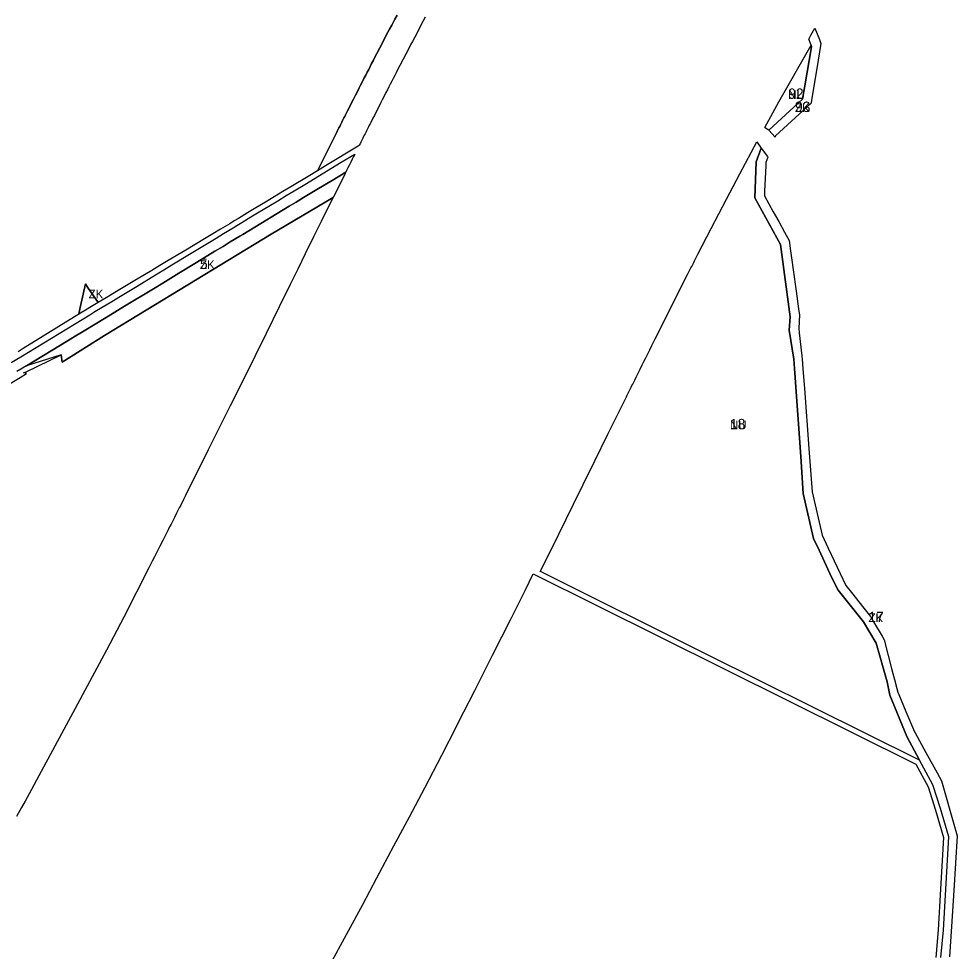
# Model space of a CAD drawing. Extents: x -537068 to -534056, y -1176840 to -1172401.
# Drawn here: x -536126 to -535584, y -1174218 to -1173679 of the extents above; entities that cross this region are included whole.
import ezdxf

# ---------------------------------------------------------------- set-up
doc = ezdxf.new("R2010")
doc.units = 0
for name, color, linetype in [('90640013', 7, 'Continuous'), ('90710013', 7, 'Continuous'), ('90710023', 7, 'Continuous'), ('90730023', 7, 'Continuous'), ('90750013', 7, 'Continuous'), ('ID_navrh', 7, 'Continuous')]:
    doc.layers.add(name, color=color, linetype=linetype)

msp = doc.modelspace()

# ---------------------------------------------------------------- linework, layer by layer
at = {"layer": '90640013'}
msp.add_lwpolyline([(-536130.48, -1173877.8), (-536124.97, -1173874.53), (-536085, -1173850.27), (-536082.06, -1173848.49), (-536071.44, -1173842.04), (-536068.28, -1173840.12), (-536057.75, -1173833.73), (-536047.04, -1173827.23), (-536042.37, -1173824.39), (-536037.66, -1173821.53), (-536027.51, -1173815.37), (-536016.81, -1173808.87), (-536012.05, -1173805.98), (-536007.72, -1173803.35), (-536002.27, -1173800.04), (-536000.01, -1173798.67), (-535997.13, -1173796.93), (-535991.99, -1173793.82), (-535987.18, -1173790.91), (-535981.54, -1173787.5), (-535976.5, -1173784.46), (-535971.51, -1173781.44), (-535967.03, -1173778.73), (-535960.88, -1173775.01), (-535939.75, -1173762.23), (-535931.97, -1173757.52), (-535932.12, -1173757.82), (-535932.63, -1173758.85), (-535933.45, -1173760.49), (-535934.27, -1173762.12), (-535935.09, -1173763.76), (-535935.91, -1173765.39), (-535936.73, -1173767.03), (-535937.15, -1173767.87), (-535945.08, -1173772.67), (-535952.93, -1173777.42), (-535961.54, -1173782.63), (-535965.74, -1173785.17), (-535969.79, -1173787.62), (-535993.13, -1173801.73), (-535996.73, -1173803.91), (-535998.32, -1173804.88), (-536003.86, -1173808.25), (-536008.07, -1173810.8), (-536012.78, -1173813.66), (-536023.5, -1173820.17), (-536033.67, -1173826.35), (-536038.31, -1173829.17), (-536042.95, -1173831.99), (-536048.32, -1173835.25), (-536065.07, -1173845.42), (-536073.11, -1173850.3), (-536080.97, -1173855.07), (-536089.33, -1173860.15), (-536093.61, -1173862.75), (-536097.5, -1173865.11), (-536121.73, -1173879.82), (-536127.22, -1173883.05)], dxfattribs=at)
at = {"layer": '90710013'}
msp.add_lwpolyline([(-536080.14, -1173843.24), (-536091.47, -1173850.03), (-536090.6, -1173846.13), (-536087.57, -1173832.53), (-536086.35, -1173834.29)], close=True, dxfattribs=at)
at = {"layer": '90710023'}
for points in [[(-535891.24, -1173678.38), (-535892.54, -1173680.85), (-535894.28, -1173684.14), (-535895.58, -1173686.61), (-535897.31, -1173689.9), (-535898.61, -1173692.37), (-535899.47, -1173694.01), (-535901.19, -1173697.3), (-535902.48, -1173699.77), (-535904.19, -1173703.06), (-535905.89, -1173706.34), (-535907.17, -1173708.81), (-535908.02, -1173710.45), (-535908.87, -1173712.1), (-535909.72, -1173713.74), (-535910.56, -1173715.38), (-535911.41, -1173717.03), (-535912.25, -1173718.67), (-535913.1, -1173720.31), (-535913.94, -1173721.96), (-535915.2, -1173724.42), (-535916.04, -1173726.06), (-535916.88, -1173727.7), (-535918.13, -1173730.16), (-535919.39, -1173732.63), (-535920.64, -1173735.09), (-535921.47, -1173736.73), (-535922.72, -1173739.19), (-535923.14, -1173740.01), (-535923.55, -1173740.83), (-535923.97, -1173741.65), (-535924.38, -1173742.47), (-535924.8, -1173743.29), (-535925.21, -1173744.11), (-535925.62, -1173744.93), (-535926.04, -1173745.75), (-535926.45, -1173746.57), (-535926.87, -1173747.39), (-535927.28, -1173748.2), (-535927.69, -1173749.02), (-535928.1, -1173749.84), (-535928.52, -1173750.66), (-535928.93, -1173751.48), (-535929.34, -1173752.3), (-535929.43, -1173752.48), (-535930.06, -1173752.86), (-535948.96, -1173764.29), (-535953.57, -1173767.08), (-535942.74, -1173745.56), (-535942.33, -1173744.74), (-535941.91, -1173743.91), (-535941.5, -1173743.09), (-535941.09, -1173742.27), (-535940.67, -1173741.45), (-535940.26, -1173740.63), (-535939.84, -1173739.81), (-535939.43, -1173738.98), (-535939.01, -1173738.16), (-535938.6, -1173737.34), (-535938.18, -1173736.52), (-535937.77, -1173735.7), (-535937.35, -1173734.87), (-535936.93, -1173734.05), (-535936.52, -1173733.23), (-535936.1, -1173732.41), (-535934.85, -1173729.94), (-535934.01, -1173728.29), (-535932.76, -1173725.82), (-535931.5, -1173723.35), (-535930.24, -1173720.88), (-535929.4, -1173719.23), (-535928.55, -1173717.59), (-535927.29, -1173715.11), (-535926.44, -1173713.47), (-535925.6, -1173711.82), (-535924.75, -1173710.17), (-535923.9, -1173708.52), (-535923.05, -1173706.87), (-535922.2, -1173705.22), (-535921.35, -1173703.57), (-535920.49, -1173701.92), (-535919.21, -1173699.44), (-535917.5, -1173696.14), (-535915.78, -1173692.84), (-535914.49, -1173690.36), (-535912.76, -1173687.06), (-535911.89, -1173685.4), (-535910.59, -1173682.92), (-535908.86, -1173679.62), (-535907.55, -1173677.14)], [(-535593.27, -1174221.64), (-535591.8, -1174205.87), (-535588.73, -1174151.97), (-535593.49, -1174135.66), (-535597.91, -1174121.88), (-535603.1, -1174112.3), (-535605.58, -1174107.71), (-535612.99, -1174094.02), (-535622.88, -1174070.09), (-535624.39, -1174062.44), (-535630.74, -1174040.13), (-535638.06, -1174027.71), (-535652.66, -1174009.5), (-535656.49, -1174001.97), (-535663.65, -1173986.37), (-535666.8, -1173979.63), (-535672.91, -1173953.63), (-535674.12, -1173932.13), (-535677.62, -1173884.09), (-535678.16, -1173875.97), (-535681.01, -1173859.2), (-535680.41, -1173851.56), (-535686.02, -1173809.63), (-535700.71, -1173782.81), (-535700.01, -1173762), (-535697.05, -1173754.05), (-535693.54, -1173758.96), (-535693.31, -1173759.31), (-535694.35, -1173762.25), (-535694.45, -1173764.25), (-535695.15, -1173778.81), (-535695.28, -1173781.53), (-535690.11, -1173790.84), (-535686.98, -1173796.48), (-535683.59, -1173802.59), (-535680.9, -1173807.44), (-535680.09, -1173813.33), (-535679.35, -1173818.68), (-535678.57, -1173824.37), (-535676.87, -1173836.7), (-535675.47, -1173846.86), (-535674.97, -1173850.53), (-535675.37, -1173858.05), (-535675.08, -1173860.72), (-535673.63, -1173873.95), (-535673.58, -1173874.6), (-535673.49, -1173875.79), (-535673.04, -1173881.63), (-535672.35, -1173890.56), (-535672.17, -1173892.95), (-535669.5, -1173927.55), (-535667.57, -1173952.61), (-535661.87, -1173977.65), (-535658.36, -1173985.16), (-535651.57, -1173999.71), (-535648.27, -1174006.76), (-535645.01, -1174010.83), (-535637.75, -1174019.91), (-535633.96, -1174024.65), (-535632.16, -1174027.72), (-535627.31, -1174035.98), (-535626.01, -1174038.2), (-535623.68, -1174047.25), (-535621.96, -1174053.94), (-535621.02, -1174057.59), (-535620.15, -1174060.99), (-535618.79, -1174066.25), (-535618.25, -1174068.37), (-535617.67, -1174069.74), (-535616.27, -1174073.01), (-535613.52, -1174079.48), (-535608.47, -1174091.3), (-535608.17, -1174091.85), (-535601.9, -1174103.21), (-535595.39, -1174115.02), (-535592.88, -1174119.58), (-535590.94, -1174126.38), (-535587.31, -1174139.14), (-535583.84, -1174151.31), (-535584.84, -1174167.22), (-535585.82, -1174182.88), (-535586.58, -1174194.95), (-535588.23, -1174221.28)]]:
    msp.add_lwpolyline(points, dxfattribs=at)
for points in [[(-535688.76, -1173747.02), (-535689.01, -1173747.62), (-535692.64, -1173743.73), (-535673.33, -1173725.68), (-535671.95, -1173718.08), (-535667.97, -1173695.42), (-535668.29, -1173694.6), (-535669.68, -1173691), (-535668.4, -1173688.75), (-535666.09, -1173684.66), (-535663.42, -1173691.33), (-535662.56, -1173693.55), (-535664.98, -1173708.05), (-535668.03, -1173726.35), (-535668.3, -1173727.97)], [(-535937.15, -1173767.87), (-535937.25, -1173768.07), (-535937.55, -1173768.66), (-535942.03, -1173777.65), (-535944.47, -1173782.56), (-535980.23, -1173803.73), (-536076.51, -1173862.38), (-536101.12, -1173877.67), (-536101.58, -1173873.52), (-536117.44, -1173878.48), (-536121.73, -1173879.82), (-536097.5, -1173865.11), (-536093.61, -1173862.75), (-536089.33, -1173860.15), (-536080.97, -1173855.07), (-536073.11, -1173850.3), (-536065.07, -1173845.42), (-536048.32, -1173835.25), (-536042.95, -1173831.99), (-536038.31, -1173829.17), (-536033.67, -1173826.35), (-536023.5, -1173820.17), (-536012.78, -1173813.66), (-536008.07, -1173810.8), (-536003.86, -1173808.25), (-535998.32, -1173804.88), (-535996.73, -1173803.91), (-535993.13, -1173801.73), (-535969.79, -1173787.62), (-535965.74, -1173785.17), (-535961.54, -1173782.63), (-535952.93, -1173777.42), (-535945.08, -1173772.67)]]:
    msp.add_lwpolyline(points, close=True, dxfattribs=at)
at = {"layer": '90730023'}
for points in [[(-535692.64, -1173743.73), (-535694.65, -1173742.49), (-535695.05, -1173742.16), (-535686.92, -1173727.29), (-535668.99, -1173695.85), (-535668.29, -1173694.6), (-535667.97, -1173695.42), (-535671.95, -1173718.08), (-535673.33, -1173725.68)], [(-535699.59, -1173750.49), (-535697.05, -1173754.05), (-535700.01, -1173762), (-535700.71, -1173782.81), (-535686.02, -1173809.63), (-535680.41, -1173851.56), (-535681.01, -1173859.2), (-535678.16, -1173875.97), (-535677.62, -1173884.09), (-535674.12, -1173932.13), (-535672.91, -1173953.63), (-535666.8, -1173979.63), (-535663.65, -1173986.37), (-535656.49, -1174001.97), (-535652.66, -1174009.5), (-535638.06, -1174027.71), (-535630.74, -1174040.13), (-535624.39, -1174062.44), (-535622.88, -1174070.09), (-535612.99, -1174094.02), (-535605.58, -1174107.71), (-535728.12, -1174046.76), (-535824.34, -1173998.89), (-535824.79, -1173998.66), (-535818.37, -1173985.73), (-535805.55, -1173959.78), (-535799.96, -1173948.44), (-535793.19, -1173934.7), (-535785.64, -1173919.36), (-535774.94, -1173897.65), (-535774.54, -1173896.85), (-535774.14, -1173896.05), (-535773.75, -1173895.25), (-535773.35, -1173894.45), (-535772.96, -1173893.65), (-535772.56, -1173892.85), (-535772.17, -1173892.05), (-535771.77, -1173891.25), (-535771.37, -1173890.45), (-535770.98, -1173889.65), (-535770.19, -1173888.05), (-535769.4, -1173886.45), (-535768.61, -1173884.85), (-535767.81, -1173883.25), (-535767.02, -1173881.66), (-535765.84, -1173879.26), (-535765.05, -1173877.67), (-535763.86, -1173875.28), (-535763.07, -1173873.69), (-535762.28, -1173872.1), (-535761.49, -1173870.5), (-535760.3, -1173868.12), (-535758.32, -1173864.15), (-535755.55, -1173858.6), (-535752.16, -1173851.81), (-535749.21, -1173845.94), (-535746.04, -1173839.64), (-535739.67, -1173827.06), (-535739.27, -1173826.28), (-535738.88, -1173825.5), (-535738.48, -1173824.72), (-535738.08, -1173823.93), (-535737.68, -1173823.15), (-535737.28, -1173822.37), (-535736.48, -1173820.8), (-535736.08, -1173820.02), (-535735.68, -1173819.24), (-535734.89, -1173817.68), (-535734.49, -1173816.9), (-535734.09, -1173816.12), (-535733.69, -1173815.34), (-535726.08, -1173800.55), (-535717.2, -1173783.55), (-535709.48, -1173768.95)]]:
    msp.add_lwpolyline(points, close=True, dxfattribs=at)
at = {"layer": '90750013'}
for points in [[(-535907.55, -1173677.14), (-535908.86, -1173679.62), (-535910.59, -1173682.92), (-535911.89, -1173685.4), (-535912.76, -1173687.06), (-535914.49, -1173690.36), (-535915.78, -1173692.84), (-535917.5, -1173696.14), (-535919.21, -1173699.44), (-535920.49, -1173701.92), (-535921.35, -1173703.57), (-535922.2, -1173705.22), (-535923.05, -1173706.87), (-535923.9, -1173708.52), (-535924.75, -1173710.17), (-535925.6, -1173711.82), (-535926.44, -1173713.47), (-535927.29, -1173715.11), (-535928.55, -1173717.59), (-535929.4, -1173719.23), (-535930.24, -1173720.88), (-535931.5, -1173723.35), (-535932.76, -1173725.82), (-535934.01, -1173728.29), (-535934.85, -1173729.94), (-535936.1, -1173732.41), (-535936.52, -1173733.23), (-535936.93, -1173734.05), (-535937.35, -1173734.87), (-535937.77, -1173735.7), (-535938.18, -1173736.52), (-535938.6, -1173737.34), (-535939.01, -1173738.16), (-535939.43, -1173738.98), (-535939.84, -1173739.81), (-535940.26, -1173740.63), (-535940.67, -1173741.45), (-535941.09, -1173742.27), (-535941.5, -1173743.09), (-535941.91, -1173743.91), (-535942.33, -1173744.74), (-535942.74, -1173745.56), (-535953.57, -1173767.08), (-535958.98, -1173770.35), (-535968.96, -1173776.39), (-535973.46, -1173779.11), (-535978.45, -1173782.13), (-535983.49, -1173785.18), (-535989.09, -1173788.57), (-535993.92, -1173791.49), (-535999.07, -1173794.61), (-536001.59, -1173796.13), (-536004.19, -1173797.69), (-536009.62, -1173800.95), (-536014.02, -1173803.59), (-536018.83, -1173806.47), (-536029.56, -1173812.91), (-536039.74, -1173819.02), (-536044.51, -1173821.88), (-536049.21, -1173824.7), (-536059.98, -1173831.16), (-536070.52, -1173837.47), (-536075.51, -1173840.47), (-536080.14, -1173843.24), (-536086.35, -1173834.29), (-536087.57, -1173832.53), (-536090.6, -1173846.13), (-536091.47, -1173850.03), (-536123.52, -1173869.83), (-536126.5, -1173871.67)], [(-536135.42, -1173892.68), (-536125.26, -1173886.52), (-536121.57, -1173884.28), (-536123.33, -1173883.88), (-536121.91, -1173883.2), (-536101.58, -1173873.52), (-536101.12, -1173877.67), (-536076.51, -1173862.38), (-535980.23, -1173803.73), (-535944.47, -1173782.56), (-535946.89, -1173787.44), (-535951.33, -1173796.4), (-535955.75, -1173805.34), (-535960.56, -1173815.08), (-535964.95, -1173824), (-535969.34, -1173832.9), (-535975.7, -1173845.81), (-535983.24, -1173861.13), (-535989.59, -1173874), (-535995.94, -1173886.85), (-536003.87, -1173902.88), (-536009.83, -1173914.87), (-536016.58, -1173928.44), (-536023.35, -1173941.97), (-536028.54, -1173952.3), (-536029.73, -1173954.68), (-536030.93, -1173957.06), (-536032.53, -1173960.23), (-536033.33, -1173961.82), (-536034.93, -1173964.99), (-536036.13, -1173967.36), (-536037.33, -1173969.74), (-536038.13, -1173971.32), (-536038.93, -1173972.9), (-536039.74, -1173974.48), (-536040.54, -1173976.06), (-536041.34, -1173977.64), (-536042.95, -1173980.8), (-536044.55, -1173983.96), (-536046.16, -1173987.11), (-536047.77, -1173990.26), (-536048.98, -1173992.62), (-536050.99, -1173996.56), (-536065.47, -1174024.98), (-536075.49, -1174044.05), (-536093.59, -1174077.8), (-536113.09, -1174114.23), (-536120.06, -1174127.01), (-536122.45, -1174131.35), (-536124.46, -1174135.08), (-536127.34, -1174140.28)], [(-535946.09, -1174225.72), (-535927.21, -1174191.1), (-535919.16, -1174175.71), (-535909.37, -1174157.17), (-535900.28, -1174140.39), (-535891.53, -1174123.6), (-535881.74, -1174104.71), (-535873, -1174087.77), (-535872.17, -1174086.14), (-535862.61, -1174067.4), (-535852.31, -1174047.03), (-535841.68, -1174025.86), (-535833.57, -1174009.59), (-535828.81, -1174000.01), (-535607.79, -1174109.96), (-535600.68, -1174123.06), (-535596.36, -1174136.54), (-535591.76, -1174152.32), (-535593.45, -1174182.15), (-535594.79, -1174205.64), (-535596.28, -1174221.57)]]:
    msp.add_lwpolyline(points, dxfattribs=at)

# ---------------------------------------------------------------- texts
at = {"layer": '90710013'}
msp.add_text('ZK', height=5, rotation=0, dxfattribs=at).set_placement((-536085.81, -1173840.86))
at = {"layer": '90710023'}
for p in [(-535677.6, -1173733.15), (-536021.4, -1173823.84), (-535635.16, -1174027.9)]:
    msp.add_text('ZK', height=5, rotation=360, dxfattribs=at).set_placement(p)
at = {"layer": '90730023'}
for rotation, p in [(360, (-535681.51, -1173725.56)), (0, (-535715.19, -1173916.47))]:
    msp.add_text('NU', height=5, rotation=rotation, dxfattribs=at).set_placement(p)
at = {"layer": 'ID_navrh'}
for s, rotation, p in [('92', 0, (-535681.51, -1173725.56)), ('93', 360, (-535677.6, -1173733.15)), ('5', 360, (-536021.4, -1173823.84)), ('18', 0, (-535715.19, -1173916.47)), ('17', 0, (-535635.16, -1174027.9))]:
    msp.add_text(s, height=6, rotation=rotation, dxfattribs=at).set_placement(p)

doc.saveas('drawing.dxf')
